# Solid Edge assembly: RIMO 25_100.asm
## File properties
Title: Zylinder
Author: ahadarics
Template: iso metric assembly.asm
Last saved by: ahadarics
Revision: 8
Application: Solid Edge
Username: ahadarics
Dokumentum tartalom típus: 1
Document Number: RIMO 25/100
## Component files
Profilrohr.par
Kit_2.par
Kolbenstange.par
Kit_1.par
Mutter_1.par
Mutter_2.par
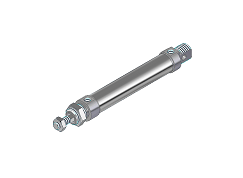
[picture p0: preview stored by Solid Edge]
